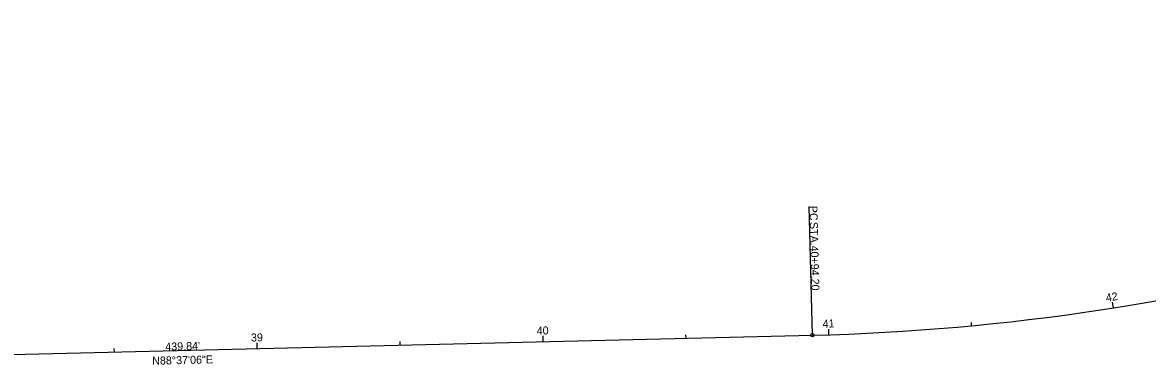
# Model space of a CAD drawing. Extents: x 1943743 to 1945350, y 152942 to 153188.
# Drawn here: x 1944563.1 to 1944956.5, y 152953.3 to 153073.2 of the extents above; entities that cross this region are included whole.
import ezdxf

# ---------------------------------------------------------------- set-up
doc = ezdxf.new("R2010")
doc.units = 0
for name, color, linetype in [('GE_X_Alignment', 7, 'Continuous'), ('GE_X_Alignment_100_Bearings', 7, 'Continuous'), ('GE_X_Alignment_100_Cardinal_Points', 7, 'Continuous'), ('GE_X_Alignment_100_Distances', 7, 'Continuous'), ('GE_X_Alignment_100_Stations', 7, 'Continuous')]:
    doc.layers.add(name, color=color, linetype=linetype)

msp = doc.modelspace()

# ---------------------------------------------------------------- linework, layer by layer
at = {"layer": 'GE_X_Alignment'}
msp.add_line((1944399.63, 152953.28), (1944839.34, 152963.89), dxfattribs=at)
msp.add_arc((1944820.08, 153762.11), 798.47, 271.38172, 300.36683, dxfattribs=at)
at = {"layer": 'GE_X_Alignment_100_Cardinal_Points'}
msp.add_line((1944839.34, 152963.87), (1944838.25, 153008.86), dxfattribs=at)
msp.add_circle((1944839.34, 152963.87), 0.6, dxfattribs=at)
at = {"layer": 'GE_X_Alignment_100_Stations'}
for p, q in [((1944944.63, 152973.42), (1944944.32, 152975.39)), ((1944895.03, 152967.17), (1944894.92, 152968.36)), ((1944845.13, 152964.04), (1944845.07, 152966.03)), ((1944645.19, 152959.2), (1944645.14, 152961.2)), ((1944695.18, 152960.41), (1944695.15, 152961.61)), ((1944745.16, 152961.61), (1944745.12, 152963.61)), ((1944795.15, 152962.82), (1944795.12, 152964.02)), ((1944595.21, 152958), (1944595.18, 152959.2))]:
    msp.add_line(p, q, dxfattribs=at)

# ---------------------------------------------------------------- texts
at = {"layer": 'GE_X_Alignment_100_Bearings'}
msp.add_text('N88°37\'06"E', height=2.8, rotation=1.3817, dxfattribs=at).set_placement((1944608.48, 152953.52))
at = {"layer": 'GE_X_Alignment_100_Cardinal_Points'}
for s, p in [('PC', (1944838.28, 153009.08)), (' STA. ', (1944838.4, 153004.48)), ('40+94.20', (1944838.62, 152995.16))]:
    msp.add_text(s, height=2.8, rotation=271.3817, dxfattribs=at).set_placement(p)
at = {"layer": 'GE_X_Alignment_100_Distances'}
msp.add_text("439.84'", height=2.8, rotation=1.3817, dxfattribs=at).set_placement((1944613.05, 152958.46))
at = {"layer": 'GE_X_Alignment_100_Stations'}
for s, rotation, p in [('42', 8.9735, (1944942.17, 152975.56)), ('41', 1.7978, (1944842.95, 152966.47)), ('39', 1.3817, (1944643.02, 152961.65)), ('40', 1.3817, (1944742.95, 152964.06))]:
    msp.add_text(s, height=2.8, rotation=rotation, dxfattribs=at).set_placement(p)

doc.saveas('drawing.dxf')
